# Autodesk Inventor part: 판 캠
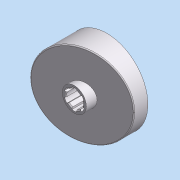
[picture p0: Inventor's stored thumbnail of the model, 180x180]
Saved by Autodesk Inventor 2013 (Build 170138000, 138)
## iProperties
Company: 한국ATC센터
Created: 2014-07
Part Number: 판 캠
Document SubType Name: 모델링
Designer: KYOUNG IL JANG
Material: Generic
Mass: 86.8262 g
Surface Area: 331.301 cm^2
Volume: 86.8262 cm^3
Density: 1 g/cm^3
변환 표준: STEP AP214IS
파일 이름: C:\Users\SeoGD\Desktop\?쒗뿕\??stp
전처리기: Build: 253, Release: 2010 SP1 - Date: Wed 07/29/2009
전송 단위: 밀리미터
불확실성: 0.01
Author: KYOUNG IL JANG
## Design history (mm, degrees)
node "작업 평면4"
sketch "스케치1"
  geometry: C1 r 44.5 at (0, 0); 1 further point
  constraints: 1 centre point, 1 coincident
  dimensions: "d25" = 89 diameter of C1
extrude "돌출1" new body sketch "스케치1" distance "d1" = 40; taper "d2" = 0 deg
sketch "스케치2"
  geometry: L1 (-44.5, 15)-(44.5, 38.847); L2 (-44.5, 0)-(-44.5, 40) reference; L3 (-44.5, 40)-(44.5, 40) reference; L4 (44.5, 0)-(44.5, 40) reference; 1 further point
  constraints: 2 end point, 2 point on line
  dimensions: "d26" = 15 distance of L2.start L1.start; "d27" = 75 deg angle of L1 L2
extrude "돌출2" cut sketch "스케치2" stored distance "d5" = 40; taper "d6" = 0 deg
node "작업 평면1"
sketch "스케치3"
  geometry: C1 r 13 at (0, 0); 1 further point
  constraints: 1 centre point, 1 coincident
  dimensions: "d9" = 26 diameter of C1
extrude "돌출3" join sketch "스케치3" distance "d10" = 38; taper "d11" = 0 deg
hole "구멍1" diameter "d14" = 18; stored, may be unused: countersink angle "d18" = 90 deg, drill point angle "d20" = 118 deg; dims "d12" = 10, "d13" = 10, "d15" = 6, "d16" = 4, "d17" = 2, "d19" = 8
feature "쉘2" dims "d29" = 5
sketch "스케치6"
  geometry: C1 r 17.5 at (0, 0); C2 r 14 at (0, 0) reference; 1 further point
  constraints: 1 centre point, 1 coincident
  dimensions: "d28" = 35 diameter of C1
extrude "돌출4" join sketch "스케치6" stored distance "d30" = 38; taper "d31" = 0 deg
fillet "모깎기1" dims "d32" = 3
chamfer "모따기1" distance "d21" = 1; stored, may be unused: second distance "d22" = 2, angle "d23" = 45 deg
feature "리브1" dims "d34" = 5, "d35" = 1, "d36" = 0
fillet "모깎기2" dims "d37" = 3
sketch "스케치8"
  geometry: L1 (2.5, 10.712)-(2.5, 8.646); L2 (-2.5, 10.712)-(-2.5, 8.646); A1 r 11 centre (0, 0) between (2.5, 10.712) and (-2.5, 10.712); A2 r 9 centre (0, 0) between (2.5, 8.646) and (-2.5, 8.646) reference; 1 further point
  constraints: 4 end point, 4 point on circle, 2 parallel, 1 centre point, 1 coincident, 1 vertical
  dimensions: "d41" = 22 diameter of A1; "d42" = 5 distance between parallel lines of L1 L2
extrude "돌출5" cut sketch "스케치8" stored distance "d43" = 38; taper "d44" = 0 deg
fillet "모깎기3" dims "d48" = 1
node "솔리드1"
node "솔리드 본체"
node "곡면 본체"
pattern_circular "원형 패턴1" dims angle "d39" = 360 deg
pattern_circular "원형 패턴2" dims angle "d46" = 360 deg
node "솔리드2"
sketch "스케치7"
  geometry: L1 (-12.374, 12.374)-(-27.931, 27.931); A1 r 39.5 centre (0, 0) between (-27.931, 27.931) and (0, 39.5) reference; 2 further points
  constraints: 2 end point, 2 point on circle, 1 point on line, 1 vertical alignment, 2 other
  dimensions: "d33" = 45 deg dimension on point (0, 0) L1.start A1.end
